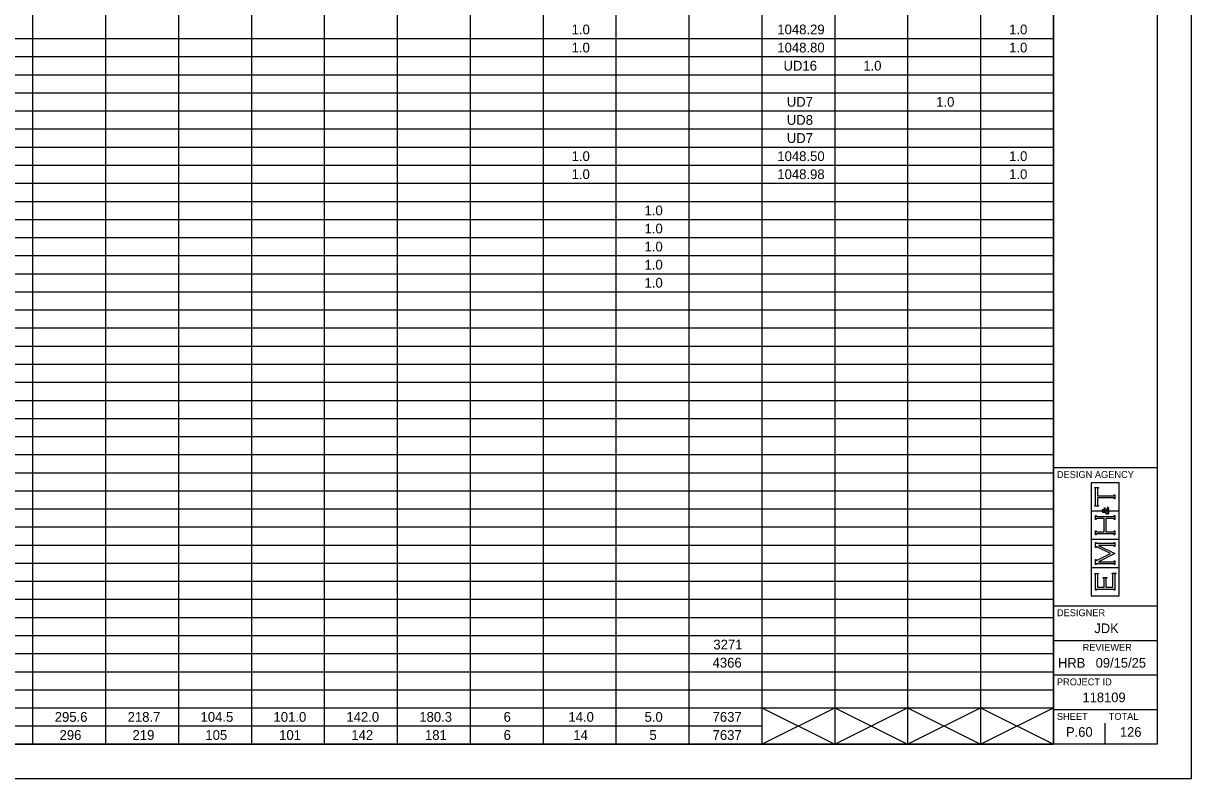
# Model space of a CAD drawing. Extents: x 0 to 34, y 0 to 22.
# Drawn here: x 17.09 to 34, y 0 to 10.93 of the extents above; entities that cross this region are included whole.
import ezdxf

# ---------------------------------------------------------------- set-up
doc = ezdxf.new("R2010")
doc.units = 0
for name, color, linetype in [('SH_Border', 7, 'Continuous'), ('SH_Cut_Line', 7, 'Continuous'), ('SH_Data', 7, 'Continuous'), ('SH_Text', 7, 'Continuous')]:
    doc.layers.add(name, color=color, linetype=linetype)

msp = doc.modelspace()

# ---------------------------------------------------------------- linework, layer by layer
at = {"layer": 'SH_Border'}
for p, q in [((32, 0.5), (32, 21.5)), ((32, 4.5), (33.5, 4.5)), ((32, 2.5), (33.5, 2.5)), ((32, 2), (33.5, 2)), ((32, 1.5), (33.5, 1.5)), ((32, 1), (33.5, 1))]:
    msp.add_line(p, q, dxfattribs=at)
msp.add_lwpolyline([(1.5, 21.5), (33.5, 21.5), (33.5, 0.5), (1.5, 0.5)], close=True, dxfattribs=at)
at = {"layer": 'SH_Cut_Line'}
msp.add_lwpolyline([(0, 0), (34, 0), (34, 22), (0, 22)], close=True, dxfattribs=at)
at = {"layer": 'SH_Data'}
for p, q in [((32.952, 4.279), (32.547, 4.279)), ((32.547, 4.279), (32.547, 3.875)), ((32.952, 3.875), (32.952, 4.279)), ((32.598, 4.204), (32.598, 4.211)), ((32.598, 4.211), (32.65, 4.211)), ((32.603, 4.203), (32.598, 4.204)), ((32.606, 4.201), (32.603, 4.203)), ((32.608, 4.199), (32.606, 4.201)), ((32.61, 4.196), (32.608, 4.199)), ((32.611, 4.192), (32.61, 4.196)), ((32.611, 4.187), (32.611, 4.192)), ((32.611, 3.968), (32.611, 4.187)), ((32.638, 4.196), (32.637, 4.192)), ((32.637, 4.192), (32.637, 4.187)), ((32.637, 4.187), (32.637, 4.093)), ((32.637, 4.093), (32.864, 4.093)), ((32.864, 4.061), (32.637, 4.061)), ((32.637, 4.061), (32.637, 3.968)), ((32.64, 4.199), (32.638, 4.196)), ((32.642, 4.201), (32.64, 4.199)), ((32.645, 4.203), (32.642, 4.201)), ((32.65, 4.204), (32.645, 4.203)), ((32.65, 4.211), (32.65, 4.204)), ((32.864, 4.093), (32.869, 4.093)), ((32.87, 4.061), (32.864, 4.061)), ((32.869, 4.093), (32.873, 4.094)), ((32.874, 4.06), (32.87, 4.061)), ((32.873, 4.094), (32.876, 4.096)), ((32.876, 4.059), (32.874, 4.06)), ((32.876, 4.096), (32.878, 4.097)), ((32.878, 4.057), (32.876, 4.059)), ((32.878, 4.097), (32.88, 4.101)), ((32.88, 4.101), (32.881, 4.106)), ((32.881, 4.106), (32.888, 4.106)), ((32.888, 4.106), (32.888, 4.048)), ((32.598, 3.95), (32.603, 3.951)), ((32.598, 3.944), (32.598, 3.95)), ((32.65, 3.944), (32.598, 3.944)), ((32.603, 3.951), (32.606, 3.953)), ((32.606, 3.953), (32.608, 3.955)), ((32.608, 3.955), (32.61, 3.958)), ((32.61, 3.958), (32.611, 3.962)), ((32.611, 3.962), (32.611, 3.968)), ((32.637, 3.968), (32.637, 3.962)), ((32.637, 3.962), (32.638, 3.958)), ((32.638, 3.958), (32.64, 3.955)), ((32.64, 3.955), (32.642, 3.953)), ((32.642, 3.953), (32.645, 3.951)), ((32.645, 3.951), (32.65, 3.95)), ((32.65, 3.95), (32.65, 3.944)), ((32.708, 3.887), (32.711, 3.89)), ((32.711, 3.89), (32.715, 3.892)), ((32.715, 3.892), (32.72, 3.892)), ((32.72, 3.892), (32.725, 3.892)), ((32.725, 3.892), (32.729, 3.89)), ((32.729, 3.89), (32.732, 3.887)), ((32.738, 3.893), (32.738, 3.922)), ((32.738, 3.922), (32.741, 3.922)), ((32.741, 3.893), (32.738, 3.893)), ((32.741, 3.922), (32.741, 3.918)), ((32.741, 3.918), (32.742, 3.915)), ((32.742, 3.896), (32.741, 3.895)), ((32.741, 3.895), (32.741, 3.893)), ((32.742, 3.915), (32.743, 3.913)), ((32.743, 3.897), (32.742, 3.896)), ((32.743, 3.913), (32.745, 3.911)), ((32.745, 3.899), (32.743, 3.897)), ((32.745, 3.911), (32.749, 3.908)), ((32.746, 3.899), (32.745, 3.899)), ((32.748, 3.899), (32.746, 3.899)), ((32.755, 3.899), (32.748, 3.899)), ((32.749, 3.908), (32.756, 3.904)), ((32.763, 3.895), (32.755, 3.899)), ((32.756, 3.904), (32.763, 3.9)), ((32.763, 3.9), (32.77, 3.896)), ((32.772, 3.887), (32.763, 3.895)), ((32.77, 3.896), (32.776, 3.891)), ((32.776, 3.891), (32.781, 3.895)), ((32.779, 3.923), (32.781, 3.926)), ((32.782, 3.922), (32.779, 3.923)), ((32.781, 3.926), (32.787, 3.924)), ((32.781, 3.895), (32.784, 3.898)), ((32.785, 3.921), (32.782, 3.922)), ((32.784, 3.898), (32.786, 3.901)), ((32.786, 3.919), (32.785, 3.921)), ((32.788, 3.917), (32.786, 3.919)), ((32.786, 3.901), (32.788, 3.904)), ((32.787, 3.924), (32.792, 3.921)), ((32.789, 3.914), (32.788, 3.917)), ((32.788, 3.904), (32.789, 3.908)), ((32.789, 3.911), (32.789, 3.914)), ((32.789, 3.908), (32.789, 3.911)), ((32.794, 3.89), (32.791, 3.886)), ((32.792, 3.921), (32.795, 3.918)), ((32.796, 3.894), (32.794, 3.89)), ((32.795, 3.918), (32.798, 3.914)), ((32.798, 3.897), (32.796, 3.894)), ((32.798, 3.914), (32.799, 3.91)), ((32.799, 3.901), (32.798, 3.897)), ((32.799, 3.91), (32.799, 3.905)), ((32.799, 3.905), (32.799, 3.901)), ((32.88, 4.053), (32.878, 4.057)), ((32.881, 4.048), (32.88, 4.053)), ((32.888, 4.048), (32.881, 4.048)), ((32.547, 3.875), (32.696, 3.875)), ((32.696, 3.869), (32.547, 3.869)), ((32.547, 3.869), (32.547, 3.465)), ((32.611, 3.749), (32.611, 3.807)), ((32.611, 3.807), (32.617, 3.807)), ((32.617, 3.749), (32.611, 3.749)), ((32.617, 3.807), (32.619, 3.802)), ((32.618, 3.754), (32.617, 3.749)), ((32.62, 3.758), (32.618, 3.754)), ((32.619, 3.802), (32.62, 3.798)), ((32.62, 3.798), (32.623, 3.797)), ((32.623, 3.76), (32.62, 3.758)), ((32.623, 3.797), (32.625, 3.795)), ((32.625, 3.761), (32.623, 3.76)), ((32.625, 3.795), (32.629, 3.794)), ((32.629, 3.762), (32.625, 3.761)), ((32.629, 3.794), (32.635, 3.794)), ((32.635, 3.762), (32.629, 3.762)), ((32.635, 3.794), (32.864, 3.794)), ((32.732, 3.762), (32.635, 3.762)), ((32.696, 3.875), (32.696, 3.869)), ((32.703, 3.879), (32.705, 3.883)), ((32.703, 3.873), (32.703, 3.879)), ((32.703, 3.868), (32.703, 3.873)), ((32.705, 3.863), (32.703, 3.868)), ((32.705, 3.883), (32.708, 3.887)), ((32.708, 3.858), (32.705, 3.863)), ((32.709, 3.879), (32.708, 3.876)), ((32.708, 3.876), (32.708, 3.873)), ((32.708, 3.873), (32.708, 3.869)), ((32.708, 3.869), (32.71, 3.866)), ((32.712, 3.853), (32.708, 3.858)), ((32.712, 3.881), (32.709, 3.879)), ((32.71, 3.866), (32.712, 3.864)), ((32.714, 3.883), (32.712, 3.881)), ((32.712, 3.864), (32.715, 3.862)), ((32.718, 3.85), (32.712, 3.853)), ((32.716, 3.884), (32.714, 3.883)), ((32.715, 3.862), (32.718, 3.861)), ((32.72, 3.884), (32.716, 3.884)), ((32.718, 3.861), (32.721, 3.861)), ((32.726, 3.85), (32.718, 3.85)), ((32.724, 3.884), (32.72, 3.884)), ((32.721, 3.861), (32.723, 3.861)), ((32.723, 3.861), (32.725, 3.862)), ((32.728, 3.882), (32.724, 3.884)), ((32.725, 3.862), (32.728, 3.862)), ((32.729, 3.85), (32.726, 3.85)), ((32.731, 3.88), (32.728, 3.882)), ((32.728, 3.862), (32.731, 3.863)), ((32.731, 3.85), (32.729, 3.85)), ((32.734, 3.877), (32.731, 3.88)), ((32.731, 3.863), (32.735, 3.865)), ((32.734, 3.851), (32.731, 3.85)), ((32.732, 3.887), (32.736, 3.883)), ((32.732, 3.572), (32.732, 3.762)), ((32.737, 3.872), (32.734, 3.877)), ((32.737, 3.852), (32.734, 3.851)), ((32.735, 3.865), (32.74, 3.867)), ((32.736, 3.883), (32.74, 3.878)), ((32.74, 3.867), (32.737, 3.872)), ((32.741, 3.853), (32.737, 3.852)), ((32.74, 3.878), (32.744, 3.869)), ((32.746, 3.855), (32.741, 3.853)), ((32.744, 3.869), (32.754, 3.875)), ((32.752, 3.844), (32.746, 3.855)), ((32.756, 3.86), (32.751, 3.857)), ((32.751, 3.857), (32.754, 3.852)), ((32.757, 3.837), (32.752, 3.844)), ((32.754, 3.875), (32.764, 3.881)), ((32.754, 3.852), (32.757, 3.848)), ((32.761, 3.863), (32.756, 3.86)), ((32.757, 3.848), (32.761, 3.845)), ((32.763, 3.833), (32.757, 3.837)), ((32.864, 3.762), (32.759, 3.762)), ((32.759, 3.762), (32.759, 3.572)), ((32.764, 3.865), (32.761, 3.863)), ((32.761, 3.845), (32.765, 3.843)), ((32.768, 3.829), (32.763, 3.833)), ((32.764, 3.881), (32.772, 3.887)), ((32.768, 3.867), (32.764, 3.865)), ((32.765, 3.843), (32.769, 3.841)), ((32.774, 3.872), (32.768, 3.867)), ((32.774, 3.827), (32.768, 3.829)), ((32.769, 3.841), (32.773, 3.841)), ((32.773, 3.841), (32.778, 3.841)), ((32.782, 3.878), (32.774, 3.872)), ((32.779, 3.827), (32.774, 3.827)), ((32.778, 3.841), (32.782, 3.843)), ((32.785, 3.827), (32.779, 3.827)), ((32.786, 3.873), (32.782, 3.878)), ((32.782, 3.843), (32.786, 3.846)), ((32.79, 3.829), (32.785, 3.827)), ((32.791, 3.886), (32.786, 3.881)), ((32.786, 3.881), (32.791, 3.876)), ((32.788, 3.869), (32.786, 3.873)), ((32.786, 3.846), (32.789, 3.849)), ((32.79, 3.867), (32.788, 3.869)), ((32.789, 3.849), (32.791, 3.853)), ((32.791, 3.864), (32.79, 3.867)), ((32.793, 3.834), (32.79, 3.829)), ((32.791, 3.876), (32.795, 3.87)), ((32.791, 3.861), (32.791, 3.864)), ((32.791, 3.859), (32.791, 3.861)), ((32.791, 3.853), (32.791, 3.859)), ((32.797, 3.838), (32.793, 3.834)), ((32.795, 3.87), (32.797, 3.866)), ((32.797, 3.866), (32.798, 3.861)), ((32.799, 3.844), (32.797, 3.838)), ((32.798, 3.861), (32.799, 3.857)), ((32.803, 3.869), (32.799, 3.875)), ((32.799, 3.875), (32.952, 3.875)), ((32.799, 3.857), (32.799, 3.852)), ((32.799, 3.852), (32.799, 3.844)), ((32.952, 3.869), (32.803, 3.869)), ((32.864, 3.794), (32.869, 3.794)), ((32.87, 3.762), (32.864, 3.762)), ((32.869, 3.794), (32.873, 3.795)), ((32.874, 3.761), (32.87, 3.762)), ((32.873, 3.795), (32.876, 3.797)), ((32.876, 3.76), (32.874, 3.761)), ((32.876, 3.797), (32.878, 3.798)), ((32.878, 3.758), (32.876, 3.76)), ((32.878, 3.798), (32.88, 3.802)), ((32.88, 3.754), (32.878, 3.758)), ((32.88, 3.802), (32.881, 3.807)), ((32.881, 3.749), (32.88, 3.754)), ((32.881, 3.807), (32.888, 3.807)), ((32.888, 3.749), (32.881, 3.749)), ((32.888, 3.807), (32.888, 3.749)), ((32.952, 3.465), (32.952, 3.869)), ((32.611, 3.527), (32.611, 3.585)), ((32.611, 3.585), (32.617, 3.585)), ((32.617, 3.585), (32.619, 3.58)), ((32.619, 3.58), (32.62, 3.576)), ((32.62, 3.576), (32.623, 3.574)), ((32.623, 3.574), (32.625, 3.573)), ((32.625, 3.573), (32.629, 3.572)), ((32.629, 3.572), (32.635, 3.572)), ((32.635, 3.572), (32.732, 3.572)), ((32.759, 3.572), (32.864, 3.572)), ((32.864, 3.572), (32.87, 3.572)), ((32.87, 3.572), (32.874, 3.573)), ((32.874, 3.573), (32.876, 3.574)), ((32.876, 3.574), (32.878, 3.576)), ((32.878, 3.576), (32.88, 3.58)), ((32.88, 3.58), (32.881, 3.585)), ((32.881, 3.585), (32.888, 3.585)), ((32.888, 3.585), (32.888, 3.527)), ((32.547, 3.465), (32.952, 3.465)), ((32.952, 3.459), (32.547, 3.459)), ((32.547, 3.459), (32.547, 3.055)), ((32.617, 3.527), (32.611, 3.527)), ((32.611, 3.345), (32.611, 3.418)), ((32.611, 3.418), (32.617, 3.418)), ((32.618, 3.532), (32.617, 3.527)), ((32.617, 3.418), (32.619, 3.412)), ((32.62, 3.536), (32.618, 3.532)), ((32.619, 3.412), (32.62, 3.409)), ((32.623, 3.537), (32.62, 3.536)), ((32.62, 3.409), (32.623, 3.407)), ((32.625, 3.539), (32.623, 3.537)), ((32.623, 3.407), (32.625, 3.405)), ((32.629, 3.54), (32.625, 3.539)), ((32.625, 3.405), (32.629, 3.405)), ((32.635, 3.54), (32.629, 3.54)), ((32.629, 3.405), (32.635, 3.405)), ((32.864, 3.54), (32.635, 3.54)), ((32.635, 3.405), (32.864, 3.405)), ((32.75, 3.5), (32.75, 3.5)), ((32.87, 3.54), (32.864, 3.54)), ((32.864, 3.405), (32.869, 3.405)), ((32.869, 3.405), (32.873, 3.405)), ((32.874, 3.539), (32.87, 3.54)), ((32.873, 3.405), (32.876, 3.407)), ((32.876, 3.538), (32.874, 3.539)), ((32.878, 3.536), (32.876, 3.538)), ((32.876, 3.407), (32.878, 3.409)), ((32.88, 3.532), (32.878, 3.536)), ((32.878, 3.409), (32.88, 3.412)), ((32.881, 3.527), (32.88, 3.532)), ((32.88, 3.412), (32.881, 3.418)), ((32.888, 3.527), (32.881, 3.527)), ((32.881, 3.418), (32.888, 3.418)), ((32.888, 3.418), (32.888, 3.36)), ((32.952, 3.055), (32.952, 3.459)), ((32.617, 3.345), (32.611, 3.345)), ((32.62, 3.352), (32.617, 3.345)), ((32.622, 3.355), (32.62, 3.352)), ((32.626, 3.355), (32.622, 3.355)), ((32.629, 3.355), (32.626, 3.355)), ((32.633, 3.353), (32.629, 3.355)), ((32.64, 3.35), (32.633, 3.353)), ((32.825, 3.257), (32.64, 3.35)), ((32.641, 3.165), (32.825, 3.257)), ((32.864, 3.373), (32.654, 3.373)), ((32.654, 3.373), (32.888, 3.255)), ((32.888, 3.255), (32.654, 3.138)), ((32.87, 3.373), (32.864, 3.373)), ((32.874, 3.372), (32.87, 3.373)), ((32.876, 3.37), (32.874, 3.372)), ((32.878, 3.369), (32.876, 3.37)), ((32.88, 3.365), (32.878, 3.369)), ((32.881, 3.36), (32.88, 3.365)), ((32.888, 3.36), (32.881, 3.36)), ((32.547, 3.055), (32.952, 3.055)), ((32.952, 3.049), (32.547, 3.049)), ((32.547, 3.049), (32.547, 2.645)), ((32.611, 3.096), (32.611, 3.168)), ((32.611, 3.168), (32.617, 3.168)), ((32.617, 3.096), (32.611, 3.096)), ((32.617, 3.168), (32.62, 3.162)), ((32.618, 3.102), (32.617, 3.096)), ((32.62, 3.105), (32.618, 3.102)), ((32.62, 3.162), (32.622, 3.158)), ((32.623, 3.107), (32.62, 3.105)), ((32.622, 3.158), (32.626, 3.158)), ((32.625, 3.109), (32.623, 3.107)), ((32.629, 3.109), (32.625, 3.109)), ((32.626, 3.158), (32.627, 3.158)), ((32.627, 3.158), (32.633, 3.161)), ((32.635, 3.109), (32.629, 3.109)), ((32.633, 3.161), (32.641, 3.165)), ((32.864, 3.109), (32.635, 3.109)), ((32.654, 3.138), (32.864, 3.138)), ((32.864, 3.138), (32.869, 3.138)), ((32.87, 3.109), (32.864, 3.109)), ((32.869, 3.138), (32.873, 3.139)), ((32.874, 3.109), (32.87, 3.109)), ((32.873, 3.139), (32.876, 3.141)), ((32.876, 3.107), (32.874, 3.109)), ((32.876, 3.141), (32.878, 3.143)), ((32.878, 3.105), (32.876, 3.107)), ((32.878, 3.143), (32.88, 3.146)), ((32.88, 3.102), (32.878, 3.105)), ((32.88, 3.146), (32.881, 3.151)), ((32.881, 3.096), (32.88, 3.102)), ((32.881, 3.151), (32.888, 3.151)), ((32.888, 3.096), (32.881, 3.096)), ((32.888, 3.151), (32.888, 3.096)), ((32.952, 2.645), (32.952, 3.049)), ((32.598, 2.962), (32.598, 2.969)), ((32.598, 2.969), (32.65, 2.969)), ((32.603, 2.961), (32.598, 2.962)), ((32.606, 2.959), (32.603, 2.961)), ((32.608, 2.957), (32.606, 2.959)), ((32.61, 2.955), (32.608, 2.957)), ((32.611, 2.951), (32.61, 2.955)), ((32.611, 2.945), (32.611, 2.951)), ((32.611, 2.725), (32.611, 2.945)), ((32.64, 2.957), (32.638, 2.955)), ((32.638, 2.955), (32.638, 2.951)), ((32.638, 2.951), (32.638, 2.945)), ((32.638, 2.945), (32.638, 2.77)), ((32.642, 2.959), (32.64, 2.957)), ((32.645, 2.961), (32.642, 2.959)), ((32.65, 2.962), (32.645, 2.961)), ((32.65, 2.969), (32.65, 2.962)), ((32.719, 2.902), (32.719, 2.908)), ((32.719, 2.908), (32.772, 2.908)), ((32.724, 2.901), (32.719, 2.902)), ((32.728, 2.899), (32.724, 2.901)), ((32.729, 2.896), (32.728, 2.899)), ((32.731, 2.894), (32.729, 2.896)), ((32.732, 2.89), (32.731, 2.894)), ((32.732, 2.884), (32.732, 2.89)), ((32.732, 2.77), (32.732, 2.884)), ((32.76, 2.894), (32.759, 2.89)), ((32.759, 2.89), (32.759, 2.884)), ((32.759, 2.884), (32.759, 2.77)), ((32.761, 2.896), (32.76, 2.894)), ((32.763, 2.899), (32.761, 2.896)), ((32.767, 2.901), (32.763, 2.899)), ((32.772, 2.902), (32.767, 2.901)), ((32.772, 2.908), (32.772, 2.902)), ((32.848, 2.965), (32.848, 2.972)), ((32.848, 2.972), (32.901, 2.972)), ((32.853, 2.964), (32.848, 2.965)), ((32.857, 2.962), (32.853, 2.964)), ((32.859, 2.96), (32.857, 2.962)), ((32.86, 2.958), (32.859, 2.96)), ((32.861, 2.953), (32.86, 2.958)), ((32.861, 2.948), (32.861, 2.953)), ((32.861, 2.77), (32.861, 2.948)), ((32.889, 2.957), (32.888, 2.953)), ((32.888, 2.953), (32.888, 2.948)), ((32.888, 2.948), (32.888, 2.725)), ((32.891, 2.96), (32.889, 2.957)), ((32.892, 2.962), (32.891, 2.96)), ((32.896, 2.964), (32.892, 2.962)), ((32.901, 2.965), (32.896, 2.964)), ((32.901, 2.972), (32.901, 2.965)), ((32.617, 2.725), (32.611, 2.725)), ((32.619, 2.73), (32.617, 2.725)), ((32.62, 2.734), (32.619, 2.73)), ((32.623, 2.735), (32.62, 2.734)), ((32.625, 2.737), (32.623, 2.735)), ((32.629, 2.738), (32.625, 2.737)), ((32.635, 2.738), (32.629, 2.738)), ((32.864, 2.738), (32.635, 2.738)), ((32.638, 2.77), (32.732, 2.77)), ((32.759, 2.77), (32.861, 2.77)), ((32.87, 2.738), (32.864, 2.738)), ((32.874, 2.737), (32.87, 2.738)), ((32.876, 2.735), (32.874, 2.737)), ((32.878, 2.734), (32.876, 2.735)), ((32.88, 2.73), (32.878, 2.734)), ((32.881, 2.725), (32.88, 2.73)), ((32.888, 2.725), (32.881, 2.725)), ((32.547, 2.645), (32.952, 2.645)), ((32.75, 0.5), (32.75, 0.8)), ((32.375, 0.675), (32.375, 0.675))]:
    msp.add_line(p, q, dxfattribs=at)
at = {"layer": 'SH_Text'}
for p, q in [((17.226, 21.5), (17.226, 0.5)), ((18.282, 21.5), (18.282, 0.5)), ((19.337, 21.5), (19.337, 0.5)), ((20.392, 21.5), (20.392, 0.5)), ((21.447, 21.5), (21.447, 0.5)), ((22.503, 21.5), (22.503, 0.5)), ((23.558, 21.5), (23.558, 0.5)), ((24.613, 21.5), (24.613, 0.5)), ((25.668, 21.5), (25.668, 0.5)), ((26.724, 21.5), (26.724, 0.5)), ((27.779, 21.5), (27.779, 0.5)), ((28.834, 21.5), (28.834, 0.5)), ((32, 21.5), (32, 0.5)), ((29.889, 19.776), (29.889, 0.5)), ((30.945, 19.776), (30.945, 0.5)), ((1.5, 10.707), (32, 10.707)), ((1.5, 10.446), (32, 10.446)), ((1.5, 10.184), (32, 10.184)), ((1.5, 9.922), (32, 9.922)), ((1.5, 9.661), (32, 9.661)), ((1.5, 9.399), (32, 9.399)), ((1.5, 9.137), (32, 9.137)), ((1.5, 8.875), (32, 8.875)), ((1.5, 8.614), (32, 8.614)), ((1.5, 8.352), (32, 8.352)), ((1.5, 8.09), (32, 8.09)), ((1.5, 7.828), (32, 7.828)), ((1.5, 7.567), (32, 7.567)), ((1.5, 7.305), (32, 7.305)), ((1.5, 7.043), (32, 7.043)), ((1.5, 6.782), (32, 6.782)), ((1.5, 6.52), (32, 6.52)), ((1.5, 6.258), (32, 6.258)), ((1.5, 5.996), (32, 5.996)), ((1.5, 5.735), (32, 5.735)), ((1.5, 5.473), (32, 5.473)), ((1.5, 5.211), (32, 5.211)), ((1.5, 4.949), (32, 4.949)), ((1.5, 4.688), (32, 4.688)), ((1.5, 4.426), (32, 4.426)), ((1.5, 4.164), (32, 4.164)), ((1.5, 3.902), (32, 3.902)), ((1.5, 3.641), (32, 3.641)), ((1.5, 3.379), (32, 3.379)), ((1.5, 3.117), (32, 3.117)), ((1.5, 2.856), (32, 2.856)), ((1.5, 2.594), (32, 2.594)), ((1.5, 2.332), (32, 2.332)), ((1.5, 2.07), (32, 2.07)), ((1.5, 1.809), (32, 1.809)), ((1.5, 1.547), (32, 1.547)), ((1.5, 1.285), (32, 1.285)), ((1.5, 1.023), (32, 1.023)), ((27.779, 0.5), (28.834, 1.023)), ((27.779, 1.023), (28.834, 0.5)), ((28.834, 0.5), (29.889, 1.023)), ((28.834, 1.023), (29.889, 0.5)), ((29.889, 0.5), (30.945, 1.023)), ((29.889, 1.023), (30.945, 0.5)), ((30.945, 0.5), (32, 1.023)), ((30.945, 1.023), (32, 0.5)), ((1.5, 0.762), (27.779, 0.762)), ((1.5, 0.5), (32, 0.5))]:
    msp.add_line(p, q, dxfattribs=at)

# ---------------------------------------------------------------- texts
at = {"layer": 'SH_Data'}
for s, height, p in [('DESIGN AGENCY', 0.1, (32.05, 4.35)), ('DESIGNER', 0.1, (32.05, 2.35)), ('JDK ', 0.14, (32.592, 2.105)), ('REVIEWER', 0.1, (32.422, 1.85)), ('HRB', 0.14, (32.066, 1.605)), ('09/15/25', 0.14, (32.611, 1.605)), ('PROJECT ID', 0.1, (32.05, 1.35)), ('118109', 0.14, (32.42, 1.105)), ('SHEET', 0.1, (32.05, 0.85)), ('TOTAL', 0.1, (32.8, 0.85)), ('P.60', 0.14, (32.182, 0.605)), ('126', 0.14, (32.962, 0.605))]:
    msp.add_text(s, height=height, dxfattribs=at).set_placement(p)
at = {"layer": 'SH_Text'}
for s, height, p in [('1.0', 0.1416, (25.027, 10.768)), ('1048.29', 0.1416, (28.004, 10.768)), ('1.0', 0.1416, (31.359, 10.768)), ('1.0', 0.1416, (25.027, 10.506)), ('1048.80', 0.1416, (28.004, 10.506)), ('1.0', 0.1416, (31.359, 10.506)), ('UD16', 0.1416, (28.094, 10.244)), ('1.0', 0.1416, (29.248, 10.244)), ('UD7', 0.1416, (28.141, 9.721)), ('1.0', 0.1416, (30.303, 9.721)), ('UD8', 0.1416, (28.141, 9.459)), ('UD7', 0.1416, (28.141, 9.197)), ('1.0', 0.1416, (25.027, 8.935)), ('1048.50', 0.1416, (28.004, 8.935)), ('1.0', 0.1416, (31.359, 8.935)), ('1.0', 0.1416, (25.027, 8.674)), ('1048.98', 0.1416, (28.004, 8.674)), ('1.0', 0.1416, (31.359, 8.674)), ('1.0', 0.1416, (26.082, 8.15)), ('1.0', 0.1416, (26.082, 7.888)), ('1.0', 0.1416, (26.082, 7.627)), ('1.0', 0.1416, (26.082, 7.365)), ('1.0', 0.1416, (26.082, 7.103)), ('3271', 0.1416, (27.078, 1.869)), ('4366', 0.1416, (27.067, 1.607)), ('295.6', 0.1416, (17.546, 0.822)), ('218.7', 0.1416, (18.601, 0.822)), ('104.5', 0.1416, (19.656, 0.822)), ('101.0', 0.1416, (20.712, 0.822)), ('142.0', 0.1416, (21.767, 0.822)), ('180.3', 0.1416, (22.822, 0.822)), ('6', 0.142, (24.042, 0.822)), ('14.0', 0.1416, (24.98, 0.822)), ('5.0', 0.1416, (26.082, 0.822)), ('7637', 0.1416, (27.067, 0.822)), ('296', 0.1416, (17.616, 0.56)), ('219', 0.1416, (18.672, 0.56)), ('105', 0.1416, (19.726, 0.56)), ('101', 0.1416, (20.794, 0.56)), ('142', 0.1416, (21.838, 0.56)), ('181', 0.1416, (22.904, 0.56)), ('6', 0.142, (24.042, 0.56)), ('14', 0.1416, (25.051, 0.56)), ('5', 0.142, (26.152, 0.56)), ('7637', 0.1416, (27.067, 0.56))]:
    msp.add_text(s, height=height, dxfattribs=at).set_placement(p)

doc.saveas('drawing.dxf')
